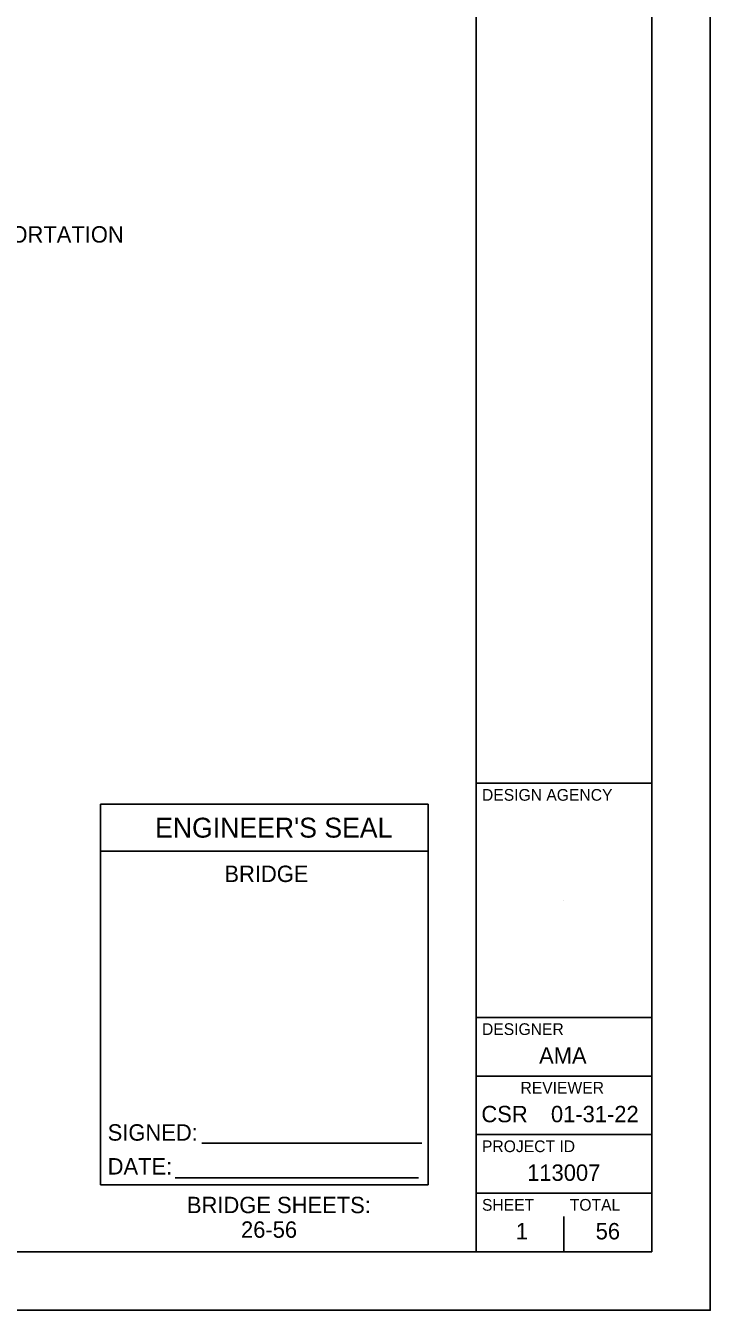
# Model space of a CAD drawing. Extents: x -4 to 116, y -17 to 29.
# Drawn here: x 76.64 to 82.48, y -14.61 to -3.64 of the extents above; entities that cross this region are included whole.
import ezdxf

# ---------------------------------------------------------------- set-up
doc = ezdxf.new("R2010")
doc.units = 0
for name, color, linetype in [('SH_Border', 7, 'Continuous'), ('SH_Cut_Line', 7, 'Continuous'), ('SH_Data', 7, 'Continuous'), ('SH_Text', 7, 'Continuous')]:
    doc.layers.add(name, color=color, linetype=linetype)

msp = doc.modelspace()

# ---------------------------------------------------------------- linework, layer by layer
at = {"layer": 'SH_Border'}
for p, q in [((80.483, -14.105), (80.483, 6.895)), ((80.483, -10.105), (81.983, -10.105)), ((80.483, -12.105), (81.983, -12.105)), ((80.483, -12.605), (81.983, -12.605)), ((80.483, -13.105), (81.983, -13.105)), ((80.483, -13.605), (81.983, -13.605))]:
    msp.add_line(p, q, dxfattribs=at)
msp.add_lwpolyline([(49.983, 6.895), (81.983, 6.895), (81.983, -14.105), (49.983, -14.105)], close=True, dxfattribs=at)
at = {"layer": 'SH_Cut_Line'}
msp.add_lwpolyline([(48.483, -14.605), (82.483, -14.605), (82.483, 7.395), (48.483, 7.395)], close=True, dxfattribs=at)
at = {"layer": 'SH_Data'}
for p, q in [((77.274, -10.285), (80.074, -10.285)), ((77.274, -13.535), (77.274, -10.285)), ((77.274, -10.285), (80.074, -10.285)), ((77.274, -10.285), (80.074, -10.285)), ((80.074, -10.285), (80.074, -13.535)), ((77.274, -10.685), (80.074, -10.685)), ((81.233, -11.105), (81.233, -11.105)), ((77.274, -13.535), (80.074, -13.535)), ((81.233, -14.105), (81.233, -13.805)), ((80.858, -13.93), (80.858, -13.93))]:
    msp.add_line(p, q, dxfattribs=at)
at = {"layer": 'SH_Text'}
for p, q in [((78.141, -13.179), (80.02, -13.179)), ((77.913, -13.475), (79.992, -13.475))]:
    msp.add_line(p, q, dxfattribs=at)

# ---------------------------------------------------------------- texts
at = {"layer": 'SH_Data'}
for s, height, p in [('DESIGN AGENCY', 0.1, (80.533, -10.255)), ("ENGINEER'S SEAL", 0.17, (77.741, -10.57)), ('BRIDGE', 0.14, (78.333, -10.949)), ('DESIGNER', 0.1, (80.533, -12.255)), ('AMA', 0.14, (81.021, -12.5)), ('REVIEWER', 0.1, (80.862, -12.755)), ('CSR', 0.14, (80.528, -13)), ('01-31-22', 0.14, (81.122, -13)), ('PROJECT ID', 0.1, (80.533, -13.255)), ('113007', 0.14, (80.919, -13.5)), ('BRIDGE SHEETS: ', 0.14, (78.013, -13.776)), ('SHEET', 0.1, (80.533, -13.755)), ('TOTAL', 0.1, (81.283, -13.755)), ('26-56', 0.14, (78.475, -13.986)), ('1', 0.14, (80.822, -14)), ('56', 0.14, (81.504, -14))]:
    msp.add_text(s, height=height, dxfattribs=at).set_placement(p)
at = {"layer": 'SH_Text'}
for s, p in [('DIRECTOR, DEPARTMENT OF TRANSPORTATION', (73.011, -5.49)), ('SIGNED: ', (77.336, -13.157)), ('DATE:', (77.336, -13.446))]:
    msp.add_text(s, height=0.14, dxfattribs=at).set_placement(p)

doc.saveas('drawing.dxf')
